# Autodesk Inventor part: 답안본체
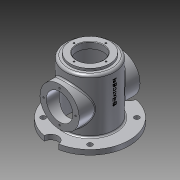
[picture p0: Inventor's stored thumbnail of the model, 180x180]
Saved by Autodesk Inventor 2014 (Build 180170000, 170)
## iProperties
Created: 2018-04
Part Number: 답안본체
Material: 알루미늄 6061
Document SubType Name: Modeling
Designer: NET
Density: 2.71 g/cm^3
Appearance: 알루미늄 - 평지
Mass: 1154.35 g
Surface Area: 1215.52 cm^2
Volume: 425.961 cm^3
Author: NET
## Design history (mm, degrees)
sketch "스케치1"
  geometry: L1 (-40, 65)-(-40, 60); L2 (-40, 60)-(-45, 60); L3 (-50, 55)-(-50, -68); L4 (-50, -68)-(0, -68); L5 (-40, 65)-(-27, 65); L6 (-27, 65)-(-27, 52); L7 (0, 65)-(0, -68); L8 (-27, 52)-(0, 52); A1 r 5 centre (-45, 55) between (-45, 60) and (-50, 55); 3 further points
  constraints: 16 end point, 5 point on line, 2 coincident, 2 horizontal, 2 perpendicular, 2 point on circle, 2 tangent, 1 centre point, 1 horizontal alignment, 1 parallel, 1 vertical
  dimensions: "d4" = 5 distance between parallel lines of L5 L2; "d5" = 133 distance between parallel lines of L4 L5; "d8" = 5 radius of A1; "d13" = 68 distance of L7.end point (0, 0); "d15" = 100 diameter of L3 L7; "d16" = 54 diameter of L6 L7; "d17" = 80 diameter of L1 L7; "d24" = 13 distance of L5.end L6.end
sketch "스케치2"
  geometry: L1 (-62, 0)-(62, 0); L2 (-62, 0)-(-62, 40); L3 (-62, 40)-(62, 40); L4 (62, 40)-(62, 0); 2 further points
  constraints: 8 end point, 2 perpendicular, 1 coincident, 1 horizontal, 1 midpoint, 1 vertical
  dimensions: "d22" = 124 distance of L2.end L3.end; "d23" = 80 diameter of L3 L1
revolve "회전3" stored, may be unused: angle "d25" = 90 deg
revolve "회전4" stored, may be unused: angle "d26" = 90 deg
sketch "스케치3"
  geometry: C1 r 50 at (0, 0) reference; C2 r 45 at (0, 0)
  constraints: 1 centre point, 1 coincident
  dimensions: "d27" = 90 diameter of C2
extrude "돌출1" cut sketch "스케치3" distance "d28" = 120; taper "d29" = 0 deg
fillet "모깎기1" dims "d30" = 3
sketch "스케치4"
  geometry: C1 r 40 at (0, 0) reference; C2 r 27 at (0, 0); 1 further point
  constraints: 1 centre point, 1 coincident, 1 vertical alignment
  dimensions: "d31" = 54 diameter of C2; "d34" = 32.5 distance of C1.centre point (0, 32.5)
extrude "돌출2" cut sketch "스케치4" stored distance "d32" = 120; taper "d33" = 0 deg
hole "구멍1" sketch "스케치4" diameter "d35" = 3.242; stored, may be unused: countersink angle "d39" = 90 deg, drill point angle "d41" = 118 deg; dims "d36" = 8, "d37" = 4, "d38" = 2, "d40" = 10
sketch "스케치5"
  geometry: C1 r 40 at (0, 0) reference; 1 further point
  constraints: 1 vertical alignment
  dimensions: "d45" = 32.5 distance of C1.centre point (0, 32.5)
hole "구멍2" sketch "스케치5" at (0, 32.5) diameter "d46" = 3.242; stored, may be unused: countersink angle "d50" = 90 deg, drill point angle "d52" = 118 deg; dims "d47" = 8, "d48" = 4, "d49" = 2, "d51" = 10
chamfer "모따기3" distance "d56" = 1; stored, may be unused: second distance "d57" = 2, angle "d58" = 45 deg
node "작업 평면1"
sketch "스케치6" dims "d89" = 135
  geometry: L1 (-47.73, 47.73)-(0, 0); L2 (0, 0)-(-80, 0); C1 r 50 at (0, 0) reference; C2 r 46 at (0, 0) reference; C3 r 15 at (0, 80); C4 r 15 at (0, -80); A1 r 80 centre (0, 0) between (0, 80) and (0, -80); 1 further point
  constraints: 4 end point, 3 centre point, 3 point on circle, 2 coincident, 2 vertical alignment, 1 horizontal, 3 other
  dimensions: "d60" = 160 diameter of A1; "d85" = 30 diameter of C3; "d86" = 30 diameter of C4; "d90" = 45 deg angle of L2 L1
  node "투영된 루프1"
extrude "바닥" join sketch "스케치6" distance "d64" = 10; taper "d65" = 0 deg
fillet "모깎기2" dims "d80" = 3
node "작업 평면2"
sketch "스케치8"
  geometry: L1 (0, -50)-(80, -50) reference; 2 further points
  constraints: 1 vertical alignment, 1 other
  dimensions: "d82" = 70 distance from line of L1 point (0, 20)
feature "엠보싱1" sketch "스케치8" dims "d83" = 0.5, "d84" = 0
extrude "돌출5" cut sketch "스케치6" distance "d87" = 10; taper "d88" = 0 deg
hole "구멍4" sketch "스케치6" diameter "d91" = 10; stored, may be unused: countersink angle "d95" = 90 deg, drill point angle "d97" = 118 deg; dims "d92" = 6, "d93" = 4, "d94" = 2, "d96" = 8
node "솔리드3"
pattern_circular "원형 패턴1" dims angle "d43" = 360 deg
mirror "대칭1"
pattern_circular "원형 패턴2" dims angle "d54" = 360 deg
pattern_circular "원형 패턴4" dims angle "d99" = 360 deg
